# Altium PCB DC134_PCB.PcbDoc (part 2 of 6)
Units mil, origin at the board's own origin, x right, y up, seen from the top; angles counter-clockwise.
Board outline 4000 x 2750 mil, 6 copper layers (L1_Top Layer, L2_GND1, L3_Signal, L4_Plane, L5_GND2, L6_Bottom Layer), stack 60.4 mil thick; 404 components, 244 nets, 1547 pads, 694 vias.
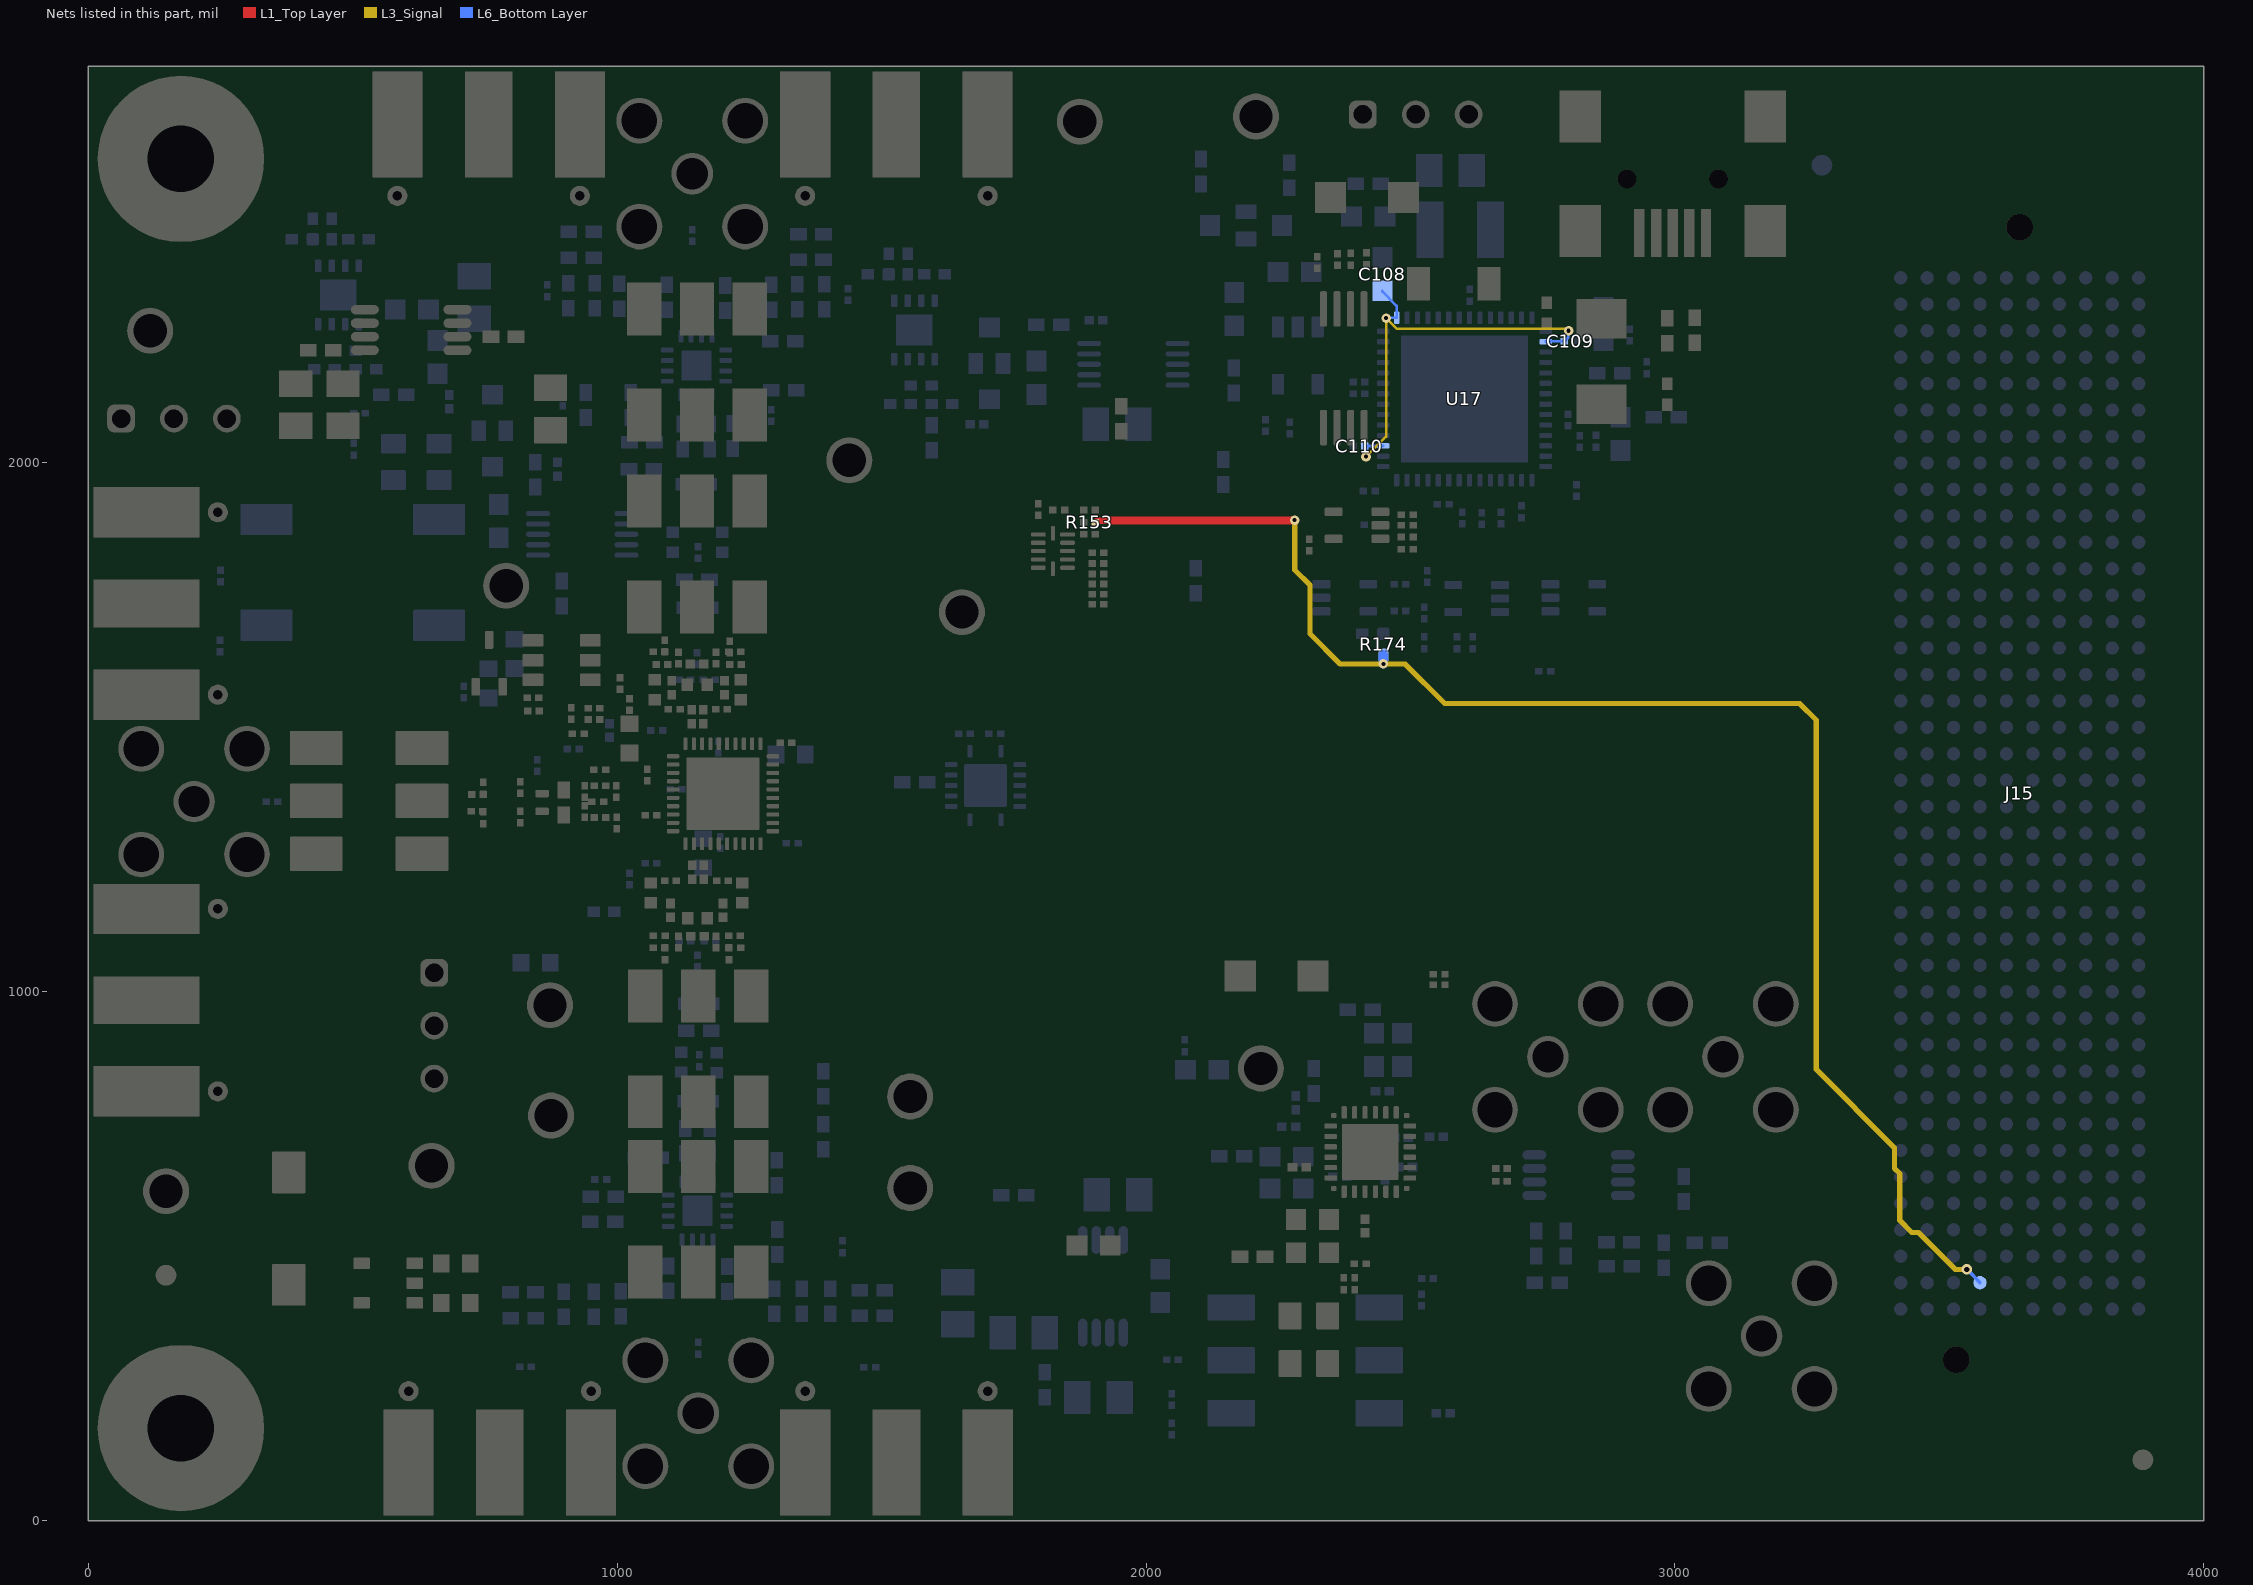
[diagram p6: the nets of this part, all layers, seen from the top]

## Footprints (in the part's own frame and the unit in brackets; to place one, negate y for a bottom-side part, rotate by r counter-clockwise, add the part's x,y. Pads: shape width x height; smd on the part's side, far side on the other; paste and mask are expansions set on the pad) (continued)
Johnson_142-0701-801#2 [mil] "Johnson Components recommended land pattern"
  rect 90x200 smd: 1(0,0)
  round 38 hole 18 mask+1.97: 2(-172.5,-135) 3(172.5,-135)
  rect 95x200 smd: 2(-172.5,0) 3(172.5,0)
  rect 95x200 smd far side: 4(-172.5,0) 5(172.5,0)
  L1_Top Layer lines w18: -172.5,0 -172.5,-135 ; 172.5,0 172.5,-135
  L6_Bottom Layer lines w18: -172.5,0 -172.5,-135 ; 172.5,0 172.5,-107 172.5,-135
  silkscreen extent -235,-170 235,100, body extent -190,-92 190,480, height 165
Keystone5010 [mil] "Keystone Multipurpose loops"
  round 87 hole 63: 1(0,0)
  silkscreen extent -70,-70 70,70, body extent -63,-63 63,62, height 319
Keystone5011 [mil] "Keystone Multipurpose loops"
  round 87 hole 63: 1(0,0)
  silkscreen extent -70,-70 70,70, body extent -63,-63 63,62, height 319
Keystone5013 [mil] "Keystone Multipurpose loops"
  round 87 hole 63: 1(0,0)
  silkscreen extent -70,-70 70,70, body extent -63,-63 63,62, height 319
Keystone_1902E [mil] "Hex Standoff, 4-40 threaded, nylon"
  round 1 on Mech4: 0(0,0)
  body extent -145,-126 146,126, height 1001
Kyocera_KC3225A [mm] "SMD, 4-Leads, Body 3.2x2.5mm"
  rrect11% 0.95x1.2 smd: 1(-0.875,1.1) 2(-0.875,-1.1) 3(0.875,-1.1) 4(0.875,1.1)
  silkscreen extent -1.7,-2.05 1.7,2.05, body extent -1.25,-1.6 1.25,1.6, height 1.01
Label_650x200 [mil] "Thermal Transfer Label"
  round 1 on Mech13: 0(0,0)
  silkscreen extent -325,-100 325,100, body extent -325,-100 325,100, height 1
LQG15WZ_02 [mm] "MuRata recommended land pattern"
  rrect29% 0.35x0.65 smd: 1(-0.425,0) 2(0.425,0)
  body extent -0.52,-0.32 0.52,0.32, height 0.6
LTST-C150_1206_Green [mm] "SMD, 2-Leads, Body 1.6x3.2mm"
  rect 1.5x1.5 smd: 1(-1.75,0) 2(1.75,0)
  silkscreen extent -3.3,-1.15 2.65,1.15, body extent -1.65,-0.85 1.65,0.85, height 1.2
MNC_CD542 [mil] "Mini-Circuits recommended land pattern 98-CD.doc rev K 11/06/06"
  rect 100x65 smd: 1(-100,100) 2(-100,0) 3(-100,-100) 4(100,-100) 5(100,0) 6(100,100)
  silkscreen extent -170,-165 170,165, body extent -141,-157 141,157, height 112
Murata_NFM31P [mm] "SMD, 3-Leads, Body 3.2x1.6mm"
  rect 0.95x1 smd paste-2 mask-2: 1(-1.725,0) 3(1.725,0)
  rect 1x0.7 smd paste-2 mask+0: 2(0,-0.65) 2(0,0.65)
  silkscreen extent -2.59,-1.2 2.59,1.2, body extent -1.7,-0.9 1.7,0.9, height 1.5
"NY PMS 440 0025 PH" [mm] "4-40 nylon screw and mounting hole"
  round 8 hole 3.2: 1(0,0)
  body extent -3.3,-3.3 3.3,3.3, height 2.69
RGE0024P [mm] "VQFN-24"
  rrect40% 0.6x0.25 smd: 1(-1.9,1.25) 2(-1.9,0.75) 3(-1.9,0.25) 4(-1.9,-0.25) 5(-1.9,-0.75) 6(-1.9,-1.25) 13(1.9,-1.25) 14(1.9,-0.75) 15(1.9,-0.25) 16(1.9,0.25) 17(1.9,0.75) 18(1.9,1.25)
  rrect40% 0.25x0.6 smd: 7(-1.25,-1.9) 8(-0.75,-1.9) 9(-0.25,-1.9) 10(0.25,-1.9) 11(0.75,-1.9) 12(1.25,-1.9) 19(1.25,1.9) 20(0.75,1.9) 21(0.25,1.9) 22(-0.25,1.9) 23(-0.75,1.9) 24(-1.25,1.9)
  rrect4% 2.7x2.7 smd paste-2.7: 25(0,0)
  rrect40% 0.25x0.25 smd: A1(-1.75,1.75) A2(-1.75,-1.75) A3(1.75,-1.75) A4(1.75,1.75)
  body extent -2,-2 2,2, height 0.9
RGT0016A_NV [mm] "QFN, 16-Leads, Body 3x3mm, Pitch 0.5mm, Thermal Pad 1.45x1.45mm, TI Recommended"
  rrect42% 0.6x0.24 smd: 1(-1.4,0.75) 2(-1.4,0.25) 3(-1.4,-0.25) 4(-1.4,-0.75) 9(1.4,-0.75) 10(1.4,-0.25) 11(1.4,0.25) 12(1.4,0.75)
  rrect42% 0.24x0.6 smd: 5(-0.75,-1.4) 6(-0.25,-1.4) 7(0.25,-1.4) 8(0.75,-1.4) 13(0.75,1.4) 14(0.25,1.4) 15(-0.25,1.4) 16(-0.75,1.4)
  rrect7% 1.34x1.34 on Bottom Paste: 17(0,0)
  rrect7% 1.45x1.45 smd paste-0.725: 17(0,0)
  silkscreen extent -1.72,-1.73 1.72,1.73, body extent -1.57,-1.57 1.58,1.58, height 1.01
RSB0040B [mm] "WQFN-40"
  rrect50% 0.6x0.2 smd: 1(-2.4,1.8) 2(-2.4,1.4) 3(-2.4,1) 4(-2.4,0.6) 5(-2.4,0.2) 6(-2.4,-0.2) 7(-2.4,-0.6) 8(-2.4,-1) 9(-2.4,-1.4) 10(-2.4,-1.8) 21(2.4,-1.8) 22(2.4,-1.4) 23(2.4,-1) 24(2.4,-0.6) 25(2.4,-0.2) 26(2.4,0.2) 27(2.4,0.6) 28(2.4,1) 29(2.4,1.4) 30(2.4,1.8)
  rrect50% 0.2x0.6 smd: 11(-1.8,-2.4) 12(-1.4,-2.4) 13(-1,-2.4) 14(-0.6,-2.4) 15(-0.2,-2.4) 16(0.2,-2.4) 17(0.6,-2.4) 18(1,-2.4) 19(1.4,-2.4) 20(1.8,-2.4) 31(1.8,2.4) 32(1.4,2.4) 33(1,2.4) 34(0.6,2.4) 35(0.2,2.4) 36(-0.2,2.4) 37(-0.6,2.4) 38(-1,2.4) 39(-1.4,2.4) 40(-1.8,2.4)
  rrect3% 3.5x3.5 smd paste-1.75: 41(0,0)
  body extent -2.5,-2.5 2.5,2.5, height 0.8
RUT0012A [mm] "QFN, 12-Leads, Body 1.7x2mm, Pitch 0.4mm, TI Recommended"
  rrect50% 0.7x0.2 smd: 1(-0.7,0.8) 2(-0.7,0.4) 3(-0.7,0) 4(-0.7,-0.4) 5(-0.7,-0.8) 7(0.7,-0.8) 8(0.7,-0.4) 9(0.7,0) 10(0.7,0.4) 11(0.7,0.8)
  rrect50% 0.2x0.7 smd: 6(0,-0.85) 12(0,0.85)
  silkscreen extent -0.9,-1.2 0.9,1.2, body extent -0.85,-1 0.85,1, height 0.55
RWA0014A [mm] "QFN, 14-Leads, Body 3.5x3.5mm, Pitch 0.5mm, Thermal Pad 2.05x2.05mm, TI Recommended"
  rrect42% 0.24x0.6 smd: 1(-0.75,1.65) 7(-0.75,-1.65) 8(0.75,-1.65) 14(0.75,1.65)
  rrect42% 0.6x0.24 smd: 2(-1.65,1) 3(-1.65,0.5) 4(-1.65,0) 5(-1.65,-0.5) 6(-1.65,-1) 9(1.65,-1) 10(1.65,-0.5) 11(1.65,0) 12(1.65,0.5) 13(1.65,1)
  rrect5% 2.05x2.05 smd paste-1.025: 15(0,0)
  silkscreen extent -1.98,-1.97 1.98,1.97, body extent -1.83,-1.83 1.82,1.82, height 0.81
Samtec_ASP-134488-01 [mm] "Connector, 1.27mm, 40x10, SMT"
  round 0.64 smd paste+0.125: A1(-5.715,24.765) A2(-5.715,23.495) A3(-5.715,22.225) A4(-5.715,20.955) A5(-5.715,19.685) A6(-5.715,18.415) A7(-5.715,17.145) A8(-5.715,15.875) A9(-5.715,14.605) A10(-5.715,13.335) A11(-5.715,12.065) A12(-5.715,10.795) A13(-5.715,9.525) A14(-5.715,8.255) A15(-5.715,6.985) A16(-5.715,5.715) A17(-5.715,4.445) A18(-5.715,3.175) A19(-5.715,1.905) A20(-5.715,0.635) A21(-5.715,-0.635) A22(-5.715,-1.905) A23(-5.715,-3.175) A24(-5.715,-4.445) A25(-5.715,-5.715) A26(-5.715,-6.985) A27(-5.715,-8.255) A28(-5.715,-9.525) A29(-5.715,-10.795) A30(-5.715,-12.065) A31(-5.715,-13.335) A32(-5.715,-14.605) A33(-5.715,-15.875) A34(-5.715,-17.145) A35(-5.715,-18.415) A36(-5.715,-19.685) A37(-5.715,-20.955) A38(-5.715,-22.225) A39(-5.715,-23.495) A40(-5.715,-24.765) B1(-4.445,24.765) B2(-4.445,23.495) B3(-4.445,22.225) B4(-4.445,20.955) B5(-4.445,19.685) B6(-4.445,18.415) B7(-4.445,17.145) B8(-4.445,15.875) B9(-4.445,14.605) B10(-4.445,13.335) B11(-4.445,12.065) B12(-4.445,10.795) B13(-4.445,9.525) B14(-4.445,8.255) B15(-4.445,6.985) B16(-4.445,5.715) B17(-4.445,4.445) B18(-4.445,3.175) B19(-4.445,1.905) B20(-4.445,0.635) B21(-4.445,-0.635) B22(-4.445,-1.905) B23(-4.445,-3.175) B24(-4.445,-4.445) B25(-4.445,-5.715) B26(-4.445,-6.985) B27(-4.445,-8.255) B28(-4.445,-9.525) B29(-4.445,-10.795) B30(-4.445,-12.065) B31(-4.445,-13.335) B32(-4.445,-14.605) B33(-4.445,-15.875) B34(-4.445,-17.145) B35(-4.445,-18.415) B36(-4.445,-19.685) B37(-4.445,-20.955) B38(-4.445,-22.225) B39(-4.445,-23.495) B40(-4.445,-24.765) C1(-3.175,24.765) C2(-3.175,23.495) C3(-3.175,22.225) C4(-3.175,20.955) C5(-3.175,19.685) C6(-3.175,18.415) C7(-3.175,17.145) C8(-3.175,15.875) C9(-3.175,14.605) C10(-3.175,13.335) C11(-3.175,12.065) C12(-3.175,10.795) C13(-3.175,9.525) C14(-3.175,8.255) C15(-3.175,6.985) C16(-3.175,5.715) C17(-3.175,4.445) C18(-3.175,3.175) C19(-3.175,1.905) C20(-3.175,0.635) C21(-3.175,-0.635) C22(-3.175,-1.905) C23(-3.175,-3.175) C24(-3.175,-4.445) C25(-3.175,-5.715) C26(-3.175,-6.985) C27(-3.175,-8.255) C28(-3.175,-9.525) C29(-3.175,-10.795) C30(-3.175,-12.065) C31(-3.175,-13.335) C32(-3.175,-14.605) C33(-3.175,-15.875) C34(-3.175,-17.145) C35(-3.175,-18.415) C36(-3.175,-19.685) C37(-3.175,-20.955) C38(-3.175,-22.225) C39(-3.175,-23.495) C40(-3.175,-24.765) D1(-1.905,24.765) D2(-1.905,23.495) D3(-1.905,22.225) D4(-1.905,20.955) D5(-1.905,19.685) D6(-1.905,18.415) D7(-1.905,17.145) D8(-1.905,15.875) D9(-1.905,14.605) D10(-1.905,13.335) D11(-1.905,12.065) D12(-1.905,10.795) D13(-1.905,9.525) D14(-1.905,8.255) D15(-1.905,6.985) D16(-1.905,5.715) D17(-1.905,4.445) D18(-1.905,3.175) D19(-1.905,1.905) D20(-1.905,0.635) D21(-1.905,-0.635) D22(-1.905,-1.905) D23(-1.905,-3.175) D24(-1.905,-4.445) D25(-1.905,-5.715) D26(-1.905,-6.985) D27(-1.905,-8.255) D28(-1.905,-9.525) D29(-1.905,-10.795) D30(-1.905,-12.065) D31(-1.905,-13.335) D32(-1.905,-14.605) D33(-1.905,-15.875) D34(-1.905,-17.145) D35(-1.905,-18.415) D36(-1.905,-19.685) D37(-1.905,-20.955) D38(-1.905,-22.225) D39(-1.905,-23.495) D40(-1.905,-24.765) E1(-0.635,24.765) E2(-0.635,23.495) E3(-0.635,22.225) E4(-0.635,20.955) E5(-0.635,19.685) E6(-0.635,18.415) E7(-0.635,17.145) E8(-0.635,15.875) E9(-0.635,14.605) E10(-0.635,13.335) E11(-0.635,12.065) E12(-0.635,10.795) E13(-0.635,9.525) E14(-0.635,8.255) E15(-0.635,6.985) E16(-0.635,5.715) E17(-0.635,4.445) E18(-0.635,3.175) E19(-0.635,1.905) E20(-0.635,0.635) E21(-0.635,-0.635) E22(-0.635,-1.905) E23(-0.635,-3.175) E24(-0.635,-4.445) E25(-0.635,-5.715) E26(-0.635,-6.985) E27(-0.635,-8.255) E28(-0.635,-9.525) E29(-0.635,-10.795) E30(-0.635,-12.065) E31(-0.635,-13.335) E32(-0.635,-14.605) E33(-0.635,-15.875) E34(-0.635,-17.145) E35(-0.635,-18.415) E36(-0.635,-19.685) E37(-0.635,-20.955) E38(-0.635,-22.225) E39(-0.635,-23.495) E40(-0.635,-24.765) F1(0.635,24.765) F2(0.635,23.495) F3(0.635,22.225) F4(0.635,20.955) F5(0.635,19.685) F6(0.635,18.415) F7(0.635,17.145) F8(0.635,15.875) F9(0.635,14.605) F10(0.635,13.335) F11(0.635,12.065) F12(0.635,10.795) F13(0.635,9.525) F14(0.635,8.255) F15(0.635,6.985) F16(0.635,5.715) F17(0.635,4.445) F18(0.635,3.175) F19(0.635,1.905) F20(0.635,0.635) F21(0.635,-0.635) F22(0.635,-1.905) F23(0.635,-3.175) F24(0.635,-4.445) F25(0.635,-5.715) F26(0.635,-6.985) F27(0.635,-8.255) F28(0.635,-9.525) F29(0.635,-10.795) F30(0.635,-12.065) F31(0.635,-13.335) F32(0.635,-14.605) F33(0.635,-15.875) F34(0.635,-17.145) F35(0.635,-18.415) F36(0.635,-19.685) F37(0.635,-20.955) F38(0.635,-22.225) F39(0.635,-23.495) F40(0.635,-24.765) G1(1.905,24.765) G2(1.905,23.495) G3(1.905,22.225) G4(1.905,20.955) G5(1.905,19.685) G6(1.905,18.415) G7(1.905,17.145) G8(1.905,15.875) G9(1.905,14.605) G10(1.905,13.335) G11(1.905,12.065) G12(1.905,10.795) G13(1.905,9.525) G14(1.905,8.255) G15(1.905,6.985) G16(1.905,5.715) G17(1.905,4.445) G18(1.905,3.175) G19(1.905,1.905) G20(1.905,0.635) G21(1.905,-0.635) G22(1.905,-1.905) G23(1.905,-3.175) G24(1.905,-4.445) G25(1.905,-5.715) G26(1.905,-6.985) G27(1.905,-8.255) G28(1.905,-9.525) G29(1.905,-10.795) G30(1.905,-12.065) G31(1.905,-13.335) G32(1.905,-14.605) G33(1.905,-15.875) G34(1.905,-17.145) G35(1.905,-18.415) G36(1.905,-19.685) G37(1.905,-20.955) G38(1.905,-22.225) G39(1.905,-23.495) G40(1.905,-24.765) H1(3.175,24.765) H2(3.175,23.495) H3(3.175,22.225) H4(3.175,20.955) H5(3.175,19.685) H6(3.175,18.415) H7(3.175,17.145) H8(3.175,15.875) H9(3.175,14.605) H10(3.175,13.335) H11(3.175,12.065) H12(3.175,10.795) H13(3.175,9.525) H14(3.175,8.255) H15(3.175,6.985) H16(3.175,5.715) H17(3.175,4.445) H18(3.175,3.175) H19(3.175,1.905) H20(3.175,0.635) H21(3.175,-0.635) H22(3.175,-1.905) H23(3.175,-3.175) H24(3.175,-4.445) H25(3.175,-5.715) H26(3.175,-6.985) H27(3.175,-8.255) H28(3.175,-9.525) H29(3.175,-10.795) H30(3.175,-12.065) H31(3.175,-13.335) H32(3.175,-14.605) H33(3.175,-15.875) H34(3.175,-17.145) H35(3.175,-18.415) H36(3.175,-19.685) H37(3.175,-20.955) H38(3.175,-22.225) H39(3.175,-23.495) H40(3.175,-24.765) J1(4.445,24.765) J2(4.445,23.495) J3(4.445,22.225) J4(4.445,20.955) J5(4.445,19.685) J6(4.445,18.415) J7(4.445,17.145) J8(4.445,15.875) J9(4.445,14.605) J10(4.445,13.335) J11(4.445,12.065) J12(4.445,10.795) J13(4.445,9.525) J14(4.445,8.255) J15(4.445,6.985) J16(4.445,5.715) J17(4.445,4.445) J18(4.445,3.175) J19(4.445,1.905) J20(4.445,0.635) J21(4.445,-0.635) J22(4.445,-1.905) J23(4.445,-3.175) J24(4.445,-4.445) J25(4.445,-5.715) J26(4.445,-6.985) J27(4.445,-8.255) J28(4.445,-9.525) J29(4.445,-10.795) J30(4.445,-12.065) J31(4.445,-13.335) J32(4.445,-14.605) J33(4.445,-15.875) J34(4.445,-17.145) J35(4.445,-18.415) J36(4.445,-19.685) J37(4.445,-20.955) J38(4.445,-22.225) J39(4.445,-23.495) J40(4.445,-24.765) K1(5.715,24.765) K2(5.715,23.495) K3(5.715,22.225) K4(5.715,20.955) K5(5.715,19.685) K6(5.715,18.415) K7(5.715,17.145) K8(5.715,15.875) K9(5.715,14.605) K10(5.715,13.335) K11(5.715,12.065) K12(5.715,10.795) K13(5.715,9.525) K14(5.715,8.255) K15(5.715,6.985) K16(5.715,5.715) K17(5.715,4.445) K18(5.715,3.175) K19(5.715,1.905) K20(5.715,0.635) K21(5.715,-0.635) K22(5.715,-1.905) K23(5.715,-3.175) K24(5.715,-4.445) K25(5.715,-5.715) K26(5.715,-6.985) K27(5.715,-8.255) K28(5.715,-9.525) K29(5.715,-10.795) K30(5.715,-12.065) K31(5.715,-13.335) K32(5.715,-14.605) K33(5.715,-15.875) K34(5.715,-17.145) K35(5.715,-18.415) K36(5.715,-19.685) K37(5.715,-20.955) K38(5.715,-22.225) K39(5.715,-23.495) K40(5.715,-24.765)
  round 1.27 hole 1.27 unplated mask+0: MH1(0,27.19) MH2(3.05,-27.19)
  silkscreen extent -8.25,-27.89 7.34,28.78, body extent -7.34,-27.89 7.34,28.78, height 7.11
SW_EVQ5PN04K [mm] "SMD, 2-Leads, Body 6x3.5mm"
  rrect6% 2x1.6 smd: 1(-2.7,0) 2(2.7,0)
  silkscreen extent -3,-1.75 3,1.75, body extent -3.6,-1.75 3.6,1.75, height 4.3
TE_87224-3 [mil] "Header, 2.54mm, 3x1, TH"
  rrect50% 52.5x52.5 hole 35: 1(-100,0)
  round 52.5 hole 35: 2(0,0) 3(100,0)
  silkscreen extent -142,-46 142,55, body extent -142,-46 142,46, height 408
TI_Stacked_Overlay_Small [mil]
  silkscreen extent -418,-98 418,98
TSSOP-8 [mm] "TSSOP, 8-Leads, Body 3.1x4.5mm (max), Pitch 0.65mm, IPC Medium Density"
  rrect50% 1.7x0.35 smd: 1(-2.85,0.975) 2(-2.85,0.325) 3(-2.85,-0.325) 4(-2.85,-0.975) 5(2.85,-0.975) 6(2.85,-0.325) 7(2.85,0.325) 8(2.85,0.975)
  silkscreen extent -2.97,-1.55 1.6,1.83, body extent -3.2,-1.55 3.2,1.55, height 1.07
VQFN-56 [mm] "VQFN, 56-Leads, Body 8x8mm, Pitch 0.5mm"
  rrect40% 0.6x0.25 smd: 1(-3.9,3.25) 2(-3.9,2.75) 3(-3.9,2.25) 4(-3.9,1.75) 5(-3.9,1.25) 6(-3.9,0.75) 7(-3.9,0.25) 8(-3.9,-0.25) 9(-3.9,-0.75) 10(-3.9,-1.25) 11(-3.9,-1.75) 12(-3.9,-2.25) 13(-3.9,-2.75) 14(-3.9,-3.25) 29(3.9,-3.25) 30(3.9,-2.75) 31(3.9,-2.25) 32(3.9,-1.75) 33(3.9,-1.25) 34(3.9,-0.75) 35(3.9,-0.25) 36(3.9,0.25) 37(3.9,0.75) 38(3.9,1.25) 39(3.9,1.75) 40(3.9,2.25) 41(3.9,2.75) 42(3.9,3.25)
  rrect40% 0.25x0.6 smd: 15(-3.25,-3.9) 16(-2.75,-3.9) 17(-2.25,-3.9) 18(-1.75,-3.9) 19(-1.25,-3.9) 20(-0.75,-3.9) 21(-0.25,-3.9) 22(0.25,-3.9) 23(0.75,-3.9) 24(1.25,-3.9) 25(1.75,-3.9) 26(2.25,-3.9) 27(2.75,-3.9) 28(3.25,-3.9) 43(3.25,3.9) 44(2.75,3.9) 45(2.25,3.9) 46(1.75,3.9) 47(1.25,3.9) 48(0.75,3.9) 49(0.25,3.9) 50(-0.25,3.9) 51(-0.75,3.9) 52(-1.25,3.9) 53(-1.75,3.9) 54(-2.25,3.9) 55(-2.75,3.9) 56(-3.25,3.9)
  rect 6.1x6.1 smd paste-6.1: 57(0,0)
  rect 0.973x0.973 on Bottom Paste: ""(-2.346,-2.346) ""(-2.346,-1.173) ""(-2.346,0) ""(-2.346,1.173) ""(-2.346,2.346) ""(-1.173,-2.346) ""(-1.173,-1.173) ""(-1.173,0) ""(-1.173,1.173) ""(-1.173,2.346) ""(0,-2.346) ""(0,-1.173) ""(0,0) ""(0,1.173) ""(0,2.346) ""(1.173,-2.346) ""(1.173,-1.173) ""(1.173,0) ""(1.173,1.173) ""(1.173,2.346) ""(2.346,-2.346) ""(2.346,-1.173) ""(2.346,0) ""(2.346,1.173) ""(2.346,2.346)
  body extent -4.04,-4.04 4.04,4.04, height 1
WEEE_Minimum [mil] "WEEElie bin"
  silkscreen extent -95,-172 99,104
XTAL_ABM3 [mm] "Abracon recommended land pattern 12.28.10"
  rect 1.9x2.4 smd: 1(-2.05,0) 2(2.05,0)
  silkscreen extent -2.67,-1.78 2.67,1.78, body extent -2.6,-1.7 2.6,1.7, height 1.3

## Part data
C1 C2 C3 C5 C6 C7 C8 C9 C10 C11 C13 C14 C15 C16 C21 C23 C24 C26 C37 C38 C40 C41 C42 C45 C48 C86 C97 C100 C105 C106 C107 C109 C110 C112 C114 C115 C116 C120 C121 C122 C123 C124: library part CMP-0064970-1, "CAP, CERM, 0.1 uF, 16 V,+/- 10%, X7R, 0201", Cap_Case=0201, Manufacturer=MuRata, Supplier Part Number 1=81-GRM033Z71C104KE4D, TempCo=X7R, Tolerance_%=10%, Value1=Unknown, Value2=16V, ValueDisplayed=0.1uF
C4 C12: library part CMP-0009763-1, "CAP, CERM, 100 pF, 25 V, +/- 10%, X7R, 0201", Cap_Case=0201, Manufacturer=MuRata, Supplier Part Number 1=490-3172-1-ND, TempCo=X7R, Tolerance_%=10%, Value1=Unknown, Value2=25V, ValueDisplayed=100pF
C17 C18 C19 C20 C22 C49 C50 C53 C54 C55 C58 C59 C61 C63 C65 C66 C102 C103: library part CMP-0006607-2, "CAP, CERM, 0.1 uF, 25 V, +/- 10%, X5R, 0402", Cap_Case=0402, Manufacturer=MuRata, Supplier Part Number 1=490-5920-1-ND, TempCo=X5R, Tolerance_%=10%, Value1=Unknown, Value2=25V, ValueDisplayed=0.1uF
C25: library part CMP-0006380-2, "CAP, CERM, 39 pF, 25 V, +/- 5%, C0G/NP0, 0402", Cap_Case=0402, Manufacturer=MuRata, Supplier Part Number 1=81-GRM1555C1E390JA1D, TempCo=C0G/NP0, Tolerance_%=5%, Value1=Unknown, Value2=25V, ValueDisplayed=39pF
C27 C31 C34 C70 C75 C79: library part CMP-0006372-2, "CAP, CERM, 1 uF, 6.3 V, +/- 20%, X5R, 0402", Cap_Case=0402, Manufacturer=MuRata, Supplier Part Number 1=490-10006-1-ND, TempCo=X5R, Tolerance_%=20%, Value1=Unknown, Value2=6.3V, ValueDisplayed=1uF
C28 C32 C35: library part CMP-0007347-5, "CAP, CERM, 4.7 uF, 25 V, +/- 10%, X5R, 0603", Cap_Case=0603, Manufacturer=MuRata, Supplier Part Number 1=490-7203-1-ND, TempCo=X5R, Tolerance_%=10%, Value1=Unknown, Value2=25V, ValueDisplayed=4.7uF
C29 C30 C33 C36 C74 C76 C78 C80: library part CMP-0009719-2, "CAP, CERM, 0.1 uF, 25 V, +/- 10%, X5R, 0201", Cap_Case=0201, Manufacturer=MuRata, Supplier Part Number 1=GRM033R61E104KE14D-ND, TempCo=X5R, Tolerance_%=10%, Value1=Unknown, Value2=25V, ValueDisplayed=0.1uF
C39 C43 C44 C47 C99 C101: library part CMP-0007497-5, "CAP, CERM, 10 uF, 10 V, +/- 20%, X7R, 0603", Cap_Case=0603, Manufacturer=MuRata, Supplier Part Number 1=81-GRM188Z71A106MA3D, TempCo=X7R, Tolerance_%=20%, Value1=Unknown, Value2=10V, ValueDisplayed=10uF
C46: library part CMP-0006624-2, "CAP, CERM, 1 uF, 6.3 V, +/- 20%, X7R, 0402", Cap_Case=0402, Manufacturer=MuRata, Supplier Part Number 1=490-9665-1-ND, TempCo=X7R, Tolerance_%=20%, Value1=Unknown, Value2=6.3V, ValueDisplayed=1uF
C51 C56: library part CMP-0006377-2, "CAP, CERM, 33 pF, 25 V, +/- 5%, C0G/NP0, 0402", Cap_Case=0402, Manufacturer=MuRata, Supplier Part Number 1=81-GRM1555C1E330JA1D, TempCo=C0G/NP0, Tolerance_%=5%, Value1=Unknown, Value2=25V, ValueDisplayed=33pF
C52 C57: library part CMP-0006425-2, "CAP, CERM, 180 pF, 50 V, +/- 5%, C0G/NP0, 0402", Cap_Case=0402, Manufacturer=MuRata, Supplier Part Number 1=490-3231-1-ND, TempCo=C0G/NP0, Tolerance_%=5%, Value1=Unknown, Value2=50V, ValueDisplayed=180pF
C60 C62 C64: library part CMP-0006607-2, "CAP, CERM, 0.1 uF, 25 V, +/- 10%, X5R, 0402", Cap_Case=0402, Manufacturer=MuRata, Supplier Part Number 1=490-5920-1-ND, TempCo=X5R, Tolerance_%=10%, Value1=Unknown, Value2=25V
C67: library part CMP-0009208-2, "CAP, CERM, 47 uF, 10 V, +/- 10%, X5R, 1210", Cap_Case=1210, Manufacturer=MuRata, Supplier Part Number 1=81-GRM32ER61A476KE20, TempCo=X5R, Tolerance_%=10%, Value1="0.001 ohm", Value2=10V, ValueDisplayed=47uF
C68 C87 C89: library part CMP-0008391-2, "CAP, CERM, 22 uF, 6.3 V, +/- 20%, X5R, 0805", Cap_Case=0805, Manufacturer="Taiyo Yuden", Supplier Part Number 1=587-1305-1-ND, TempCo=X5R, Tolerance_%=20%, Value1=Unknown, Value2=6.3V, ValueDisplayed=22uF
C69: library part CMP-0007318-5, "CAP, CERM, 10 uF, 10 V, +/- 20%, X5R, 0603", Cap_Case=0603, Manufacturer=MuRata, TempCo=X5R, Tolerance_%=20%, Value1=Unknown, Value2=10V, ValueDisplayed=10uF
C71 C72: library part capcc03298, "CAP CER 4.7UF 10V X5R 0402", Manufacturer="TDK Corporation", Operating Temperature="-55°C ~ 85°C", Package / Case=0402, Ratings=-, Temperature Coefficient=X5R, Tolerance=±10%, Voltage - Rated=10V
C73 C77: library part capcc02726, "CAP CER 1UF 10V X6S 0402", Manufacturer="TDK Corporation", Operating Temperature="-55°C ~ 105°C", Package / Case=0402, Ratings=-, Temperature Coefficient=X6S, Tolerance=±10%, Voltage - Rated=10V
C81 C82 C91 C92: library part CMP-0007311-5, "CAP, CERM, 4.7 uF, 6.3 V, +/- 10%, X5R, 0603", Cap_Case=0603, Manufacturer=MuRata, Supplier Part Number 1=490-3297-1-ND, TempCo=X5R, Tolerance_%=10%, Value1="0.005 ohm", Value2=6.3V, ValueDisplayed=4.7uF
C83 C84: library part CMP-0006831-4, "CAP, CERM, 1 uF, 16 V, +/- 10%, X7R, 0603", Cap_Case=0603, Manufacturer="Wurth Elektronik", Supplier Part Number 1=710-885012206052, TempCo=X7R, Tolerance_%=10%, Value1=Unknown, Value2=16V, ValueDisplayed=1uF
C85 C88 C90 C93 C94 C95 C96: library part CMP-0007691-2, "CAP, CERM, 10 uF, 10 V, +/- 10%, X7R, 0805", Cap_Case=0805, Manufacturer="Wurth Elektronik", Supplier Part Number 1=710-885012207026, TempCo=X7R, Tolerance_%=10%, Value1=Unknown, Value2=10V, ValueDisplayed=10uF
C98: library part CMP-0009762-1, "CAP, CERM, 100 pF, 25 V, +/- 5%, C0G/NP0, 0201", Cap_Case=0201, Manufacturer=MuRata, Supplier Part Number 1=81-GRM033R71E101JA1D, TempCo=C0G/NP0, Tolerance_%=5%, Value1=Unknown, Value2=25V, ValueDisplayed=100pF
C104: library part CMP-0064957-1, "CAP, CERM, 100 uF, 6.3 V,+/- 20%, X5R, 1206", Cap_Case=1206, Manufacturer=TDK, Supplier Part Number 1=445-6008-1-ND, TempCo=X5R, Tolerance_%=20%, Value1=Unknown, Value2=6.3V, ValueDisplayed=100uF
C108: library part CMP-0007008-5, "CAP, CERM, 3.3 uF, 25 V, +/- 10%, X5R, 0603", Cap_Case=0603, Manufacturer=TDK, Supplier Part Number 1=445-14141-1-ND, TempCo=X5R, Tolerance_%=10%, Value1=Unknown, Value2=25V, ValueDisplayed=3.3uF
C111 C113: library part CMP-0064936-4, "CAP, CERM, 4.7 uF, 16 V,+/- 10%, X7R, 0603", Cap_Case=0603, Manufacturer=MuRata, TempCo=X7R, Tolerance_%=10%, Value1=Unknown, Value2=16V, ValueDisplayed=4.7uF
C117: library part CMP-0085847-1, "CAP, CERM, 100 pF, 25 V,+/- 5%, C0G/NP0, 0201", Cap_Case=0201, Manufacturer=Yageo, TempCo=C0G/NP0, Tolerance_%=5%, Value2=25V, ValueDisplayed=100pF
C118 C119: library part CMP-0006247-2, "CAP, CERM, 18 pF, 50 V, +/- 5%, C0G/NP0, 0402", Cap_Case=0402, Manufacturer=TDK, Supplier Part Number 1=445-1238-1-ND, TempCo=C0G/NP0, Tolerance_%=5%, Value1=Unknown, Value2=50V, ValueDisplayed=18pF
C125 C126: library part capcc05563, "CAP CER 10000PF 10V X7R 0402", Manufacturer="KYOCERA AVX", Operating Temperature="-55°C ~ 125°C", Package / Case=0402, Ratings=-, Temperature Coefficient=X7R, Tolerance=±5%, Voltage - Rated=10V
D1 D2: library part CMP-0002920-2, "LED, Green, SMD", Color=Green, Manufacturer=LiteOn, Value1=W, Value2=2V
FB1 FB2 FB3: library part CMP-0001934-2, "FILTER LC HIGH FREQ 27uF 1206", Manufacturer=MuRata, Supplier Part Number 1=490-6984-1-ND
FID1 FID2 FID3: library part CMP-0077181-1, "Fiducial mark.  There is nothing to buy or mount.", Manufacturer=N/A
H1 H2: library part CMP-0003617-1, "Machine Screw, Round, #4-40 x 1/4, Nylon, Philips panhead", Manufacturer="B&F Fastener Supply", Supplier Part Number 1=H542-ND
H3 H4: library part CMP-0003611-1, Manufacturer=Keystone, Supplier Part Number 1=36-1902E-ND
J1 J3 J4 J6 J8 J10: library part CMP-0055828-1, "Connector, End launch SMA, 50 ohm, SMT", Manufacturer="Cinch Connectivity", Supplier Part Number 1=J502-ND
J2 J5 J7 J9 J11 J12: library part CMP-0055833-1, "SMA Straight Jack, Gold, 50 Ohm, TH", Manufacturer="Amphenol RF", Supplier Part Number 1=ARFX1231-ND
J13 J14 J16: library part CMP-0078139-1, "Header, 2.54mm, 3x1, Gold, TH", Color=Black, Current_A=3A, Manufacturer="TE Connectivity", Supplier Part Number 1=A26545-ND, Voltage_V=750V
J15: library part CMP-0075635-1, "Connector, 1.27mm, 40x10, Black, SMT", Color=Black, Manufacturer=Samtec, Supplier Part Number 1=79X1313
J17: library part CMP-0054920-2, "Connector, Receptacle, Mini-USB Type B, R/A, Top Mount SMT", Manufacturer="TE Connectivity", Supplier Part Number 1=A31727CT-ND
L1 L2 L3 L4 L5 L6: library part CMP-0058650-1, "Inductor, Multilayer, Air Core, 180 nH, 0.14 A, 3.38 ohm, SMD", Manufacturer=MuRata, Supplier Part Number 1=490-2638-1-ND, Value1="3.38 ohm", Value2=0.14A, ValueDisplayed=180nH
L7: library part CMP-0080278-3, "Inductor, Multilayer, Air Core, 43 nH, 0.19 A, 1.6 ohm, AEC-Q200 Grade 1, SMD", Manufacturer=MuRata, Value1="1.6 ohm", Value2=0.19A, ValueDisplayed=43nH
L8 L9 L10: library part CMP-0077879-1, "Ferrite Bead, 120 ohm @ 100 MHz, 1.9 A, 0603", Manufacturer=MuRata, Supplier Part Number 1=490-13261-1-ND, Value1="0.04 ohm", Value2=1.9A, ValueDisplayed="120 ohm"
L11 L12 L13 L14: library part CMP-0058651-1, "Inductor, Multilayer, Air Core, 220 nH, 0.12 A, 3.77 ohm, SMD", Manufacturer=MuRata, Supplier Part Number 1=490-2639-1-ND, Value1="3.77 ohm", Value2=0.12A, ValueDisplayed=220nH
L15 L18 L19 L20: library part CMP-0003214-1, "Ferrite Bead, 120 ohm @ 100 MHz, 0.5 A, 0402", Manufacturer="Wurth Elektronik", Supplier Part Number 1=710-74279271, Value1="0.2 ohm", Value2=0.5A, ValueDisplayed="120 ohm"
LBL1: library part CMP-0003625-1, "Thermal Transfer Printable Labels, 0.650\" W x 0.200\" H - 10,000 per roll", Manufacturer=Brady, Supplier Part Number 1=97C5133
Logo1: library part CMP-0074838-1, "Texas Instrument Corporate Signature"
Logo2: library part CMP-0074844-1
Logo3: library part CMP-0074847-1, "FCC_disclaimer"
Logo4: library part CMP-0074769-1
R1 R2 R3 R6 R9 R10 R13 R14 R15 R16 R17 R20 R23 R24 R27 R28 R31 R32 R33 R35 R36 R40 R41 R43 R45 R51 R52 R53 R54 R55 R60 R61 R63 R64 R68 R70 R75 R76 R77 R93 R95 R108 R112 R130 R135 R136 R137 R138 R139 R141 R142 R143 R144 R145 R146 R148 R151 R152 R153 R158 R159 R163 R167 R168 R169 R170: library part CMP-0027008-4, "RES, 0, 5%, 0.05 W, 0201", Manufacturer=Vishay-Dale, Power_W=50mW, Supplier Part Number 1=72M6743, TempCo=ppm/C, Tolerance_%=5%, Value2=0.05W, Value_Code=0000, ValueDisplayed=0
R4 R11 R18 R25: library part CMP-0028006-1, "RES, 33.0, 1%, 0.05 W, 0201", Manufacturer="Yageo America", Power_W=50mW, Supplier Part Number 1=603-RC0201FR-7D33RL, TempCo="200 ppm/C", Tolerance_%=1%, Value2=0.05W, Value_Code=33R0, ValueDisplayed=33.0
R5 R12 R19 R26 R48 R49: library part CMP-0027946-1, "RES, 10.0, 1%, 0.05 W, 0201", Manufacturer="Yageo America", Power_W=50mW, Supplier Part Number 1=603-RC0201FR-7D10RL, TempCo="350 ppm/C", Tolerance_%=1%, Value2=0.05W, Value_Code=10R0, ValueDisplayed=10.0
R7 R8 R21 R22: library part CMP-0027524-1, "RES, 25.5, 1%, 0.05 W, 0201", Manufacturer="Yageo America", Power_W=50mW, Supplier Part Number 1=YAG2539CT-ND, TempCo="200 ppm/C", Tolerance_%=1%, Value2=0.05W, Value_Code=25R5, ValueDisplayed=25.5
R29 R30 R46 R47 R50 R65 R67 R140: library part CMP-0028028-1, "RES, 49.9, 1%, 0.05 W, 0201", Manufacturer="Yageo America", Power_W=50mW, Supplier Part Number 1=603-RC0201FR-7D49R9L, TempCo="200 ppm/C", Tolerance_%=1%, Value2=0.05W, Value_Code=49R9, ValueDisplayed=49.9
R34 R42: library part CMP-0026453-2, "RES, 56.2 k, 1%, 0.063 W, AEC-Q200 Grade 0, 0402", Manufacturer=Vishay-Dale, Power_W=63mW, Supplier Part Number 1=541-56.2KLCT-ND, TempCo="100 ppm/C", Tolerance_%=1%, Value2=0.063W, Value_Code=56k2, ValueDisplayed=56.2k
R37 R44: library part CMP-0026196-2, "RES, 24.9 k, 1%, 0.063 W, AEC-Q200 Grade 0, 0402", Manufacturer=Vishay-Dale, Power_W=63mW, Supplier Part Number 1=541-24.9KLCT-ND, TempCo="100 ppm/C", Tolerance_%=1%, Value2=0.063W, Value_Code=24k9, ValueDisplayed=24.9k
R38 R39 R66 R69 R127: library part CMP-0027453-1, "RES, 1.00 k, 1%, 0.05 W, 0201", Manufacturer="Yageo America", Power_W=50mW, Supplier Part Number 1=311-1KMCT-ND, TempCo="200 ppm/C", Tolerance_%=1%, Value2=0.05W, Value_Code=1k00, ValueDisplayed=1.00k
R56 R58 R62 R71 R72 R73 R74: library part CMP-0028031-1, "RES, 4.70 k, 1%, 0.05 W, 0201", Manufacturer="Yageo America", Power_W=50mW, Supplier Part Number 1=603-RC0201FR-7D4K7L, TempCo="200 ppm/C", Tolerance_%=1%, Value2=0.05W, Value_Code=4k70, ValueDisplayed=4.70k
R57: library part CMP-0023343-3, "RES, 0, 1%, 0.1 W, AEC-Q200 Grade 0, 0603", Manufacturer="Stackpole Electronics Inc", Power_W=100mW, Supplier Part Number 1=RMCF0603ZT0R00CT-ND, TempCo=ppm/C, Tolerance_%=1%, Value2=0.1W, Value_Code=0
R59 R114: library part CMP-0026725-1, "RES, 1.00 k, 1%, 0.0625 W, 0402", Manufacturer="Yageo America", Power_W=62.5mW, Supplier Part Number 1=311-1.00KLRCT-ND, TempCo="100 ppm/C", Tolerance_%=1%, Value2=0.0625W, Value_Code=1k00, ValueDisplayed=1.00k
R78 R79: library part CMP-0065361-1, "RES, 0, 5%, .05 W, AEC-Q200 Grade 0, 0201", Manufacturer=Panasonic, Power_W=50mW, Supplier Part Number 1=P15979CT-ND, TempCo=ppm/C, Tolerance_%=5%, Value2=.05W, Value_Code=0000, ValueDisplayed=0
R80 R96 R97: library part CMP-0026402-2, "RES, 499, 1%, 0.063 W, AEC-Q200 Grade 0, 0402", Manufacturer=Vishay-Dale, Power_W=63mW, Supplier Part Number 1=541-499LCT-ND, TempCo="100 ppm/C", Tolerance_%=1%, Value2=0.063W, Value_Code=499R, ValueDisplayed=499
R81 R85 R94 R98 R102 R111: library part CMP-0026822-3, "RES, 0, 5%, 0.063 W, AEC-Q200 Grade 0, 0402", Manufacturer=Vishay-Dale, Power_W=63mW, Supplier Part Number 1=541-0.0JCT-ND, TempCo="200 ppm/C", Tolerance_%=5%, Value2=0.063W, Value_Code=0000, ValueDisplayed=0
R82 R91 R99 R109: library part CMP-0026462-2, "RES, 59.0, 1%, 0.063 W, AEC-Q200 Grade 0, 0402", Manufacturer=Vishay-Dale, Power_W=63mW, Supplier Part Number 1=541-59.0LCT-ND, TempCo="100 ppm/C", Tolerance_%=1%, Value2=0.063W, Value_Code=59R0, ValueDisplayed=59.0
R83 R92 R100 R110: library part CMP-0026404-2, "RES, 49.9, 1%, 0.063 W, AEC-Q200 Grade 0, 0402", Manufacturer=Vishay-Dale, Power_W=63mW, Supplier Part Number 1=541-49.9LCT-ND, TempCo="100 ppm/C", Tolerance_%=1%, Value2=0.063W, Value_Code=49R9, ValueDisplayed=49.9
R84 R90 R101 R107: library part CMP-0026320-2, "RES, 37.4, 1%, 0.063 W, AEC-Q200 Grade 0, 0402", Manufacturer=Vishay-Dale, Power_W=63mW, Supplier Part Number 1=541-37.4LCT-ND, TempCo="100 ppm/C", Tolerance_%=1%, Value2=0.063W, Value_Code=37R4, ValueDisplayed=37.4
R86 R88 R103 R105: library part CMP-0026159-2, "RES, 200, 1%, 0.063 W, AEC-Q200 Grade 0, 0402", Manufacturer=Vishay-Dale, Power_W=63mW, Supplier Part Number 1=541-200LCT-ND, TempCo="100 ppm/C", Tolerance_%=1%, Value2=0.063W, Value_Code=200R, ValueDisplayed=200
R87 R104: library part CMP-0026382-2, "RES, 442, 1%, 0.063 W, AEC-Q200 Grade 0, 0402", Manufacturer=Vishay-Dale, Power_W=63mW, Supplier Part Number 1=541-442LCT-ND, TempCo="100 ppm/C", Tolerance_%=1%, Value2=0.063W, Value_Code=442R, ValueDisplayed=442
R89 R106: library part CMP-0026700-1, "RES, 4.70 k, 1%, 0.1 W, 0402", Manufacturer=Panasonic, Power_W=100mW, Supplier Part Number 1=P4.70KLCT-ND, TempCo="100 ppm/C", Tolerance_%=1%, Value2=0.1W, Value_Code=4k70, ValueDisplayed=4.70k
R113: library part CMP-0026402-2, "RES, 499, 1%, 0.063 W, AEC-Q200 Grade 0, 0402", Manufacturer=Vishay-Dale, Power_W=63mW, Supplier Part Number 1=541-499LCT-ND, TempCo="100 ppm/C", Tolerance_%=1%, Value2=0.063W, Value_Code=499R
R115 R117: library part CMP-0026822-3, "RES, 0, 5%, 0.063 W, AEC-Q200 Grade 0, 0402", Manufacturer=Vishay-Dale, PartNumber=CRCW04020000Z0ED, Power_W=63mW, Supplier Part Number 1=541-0.0JCT-ND, TempCo="200 ppm/C", Tolerance_%=5%, Value2=0.063W, Value_Code=0000, ValueDisplayed=0
R116 R118 R121 R122 R175 R176: library part RSMD040201951, "RES SMD 10K OHM 1% 1/10W 0402", Manufacturer="Panasonic Electronic Components", Operating Temperature="-55°C ~ 155°C", Package / Case=0402, Power (Watts)="0.1W, 1/10W", Ratings=AEC-Q200, Temperature Coefficient=±100ppm/°C, Tolerance=±1%
R119 R120: library part RSMD040202026, "RES SMD 12.7K OHM 1% 1/10W 0402", Manufacturer="Panasonic Electronic Components", Operating Temperature="-55°C ~ 155°C", Package / Case=0402, Power (Watts)="0.1W, 1/10W", Ratings=AEC-Q200, Temperature Coefficient=±100ppm/°C, Tolerance=±1%
R123 R124 R125 R126: library part CMP-0027007-2, "RES, 0, 5%, 0.063 W, AEC-Q200 Grade 0, 0402", Manufacturer="KOA Speer", Power_W=63mW, Supplier Part Number 1=660-RK73Z1ETTP, TempCo=ppm/C, Tolerance_%=5%, Value2=0.063W, Value_Code=0000, ValueDisplayed=0
R128: library part CMP-0027731-1, "RES, 499, 1%, 0.05 W, 0201", Manufacturer="Yageo America", Power_W=50mW, Supplier Part Number 1=YAG2700CT-ND, TempCo="200 ppm/C", Tolerance_%=1%, Value2=0.05W, Value_Code=499R, ValueDisplayed=499
R129: library part CMP-0027094-3, "RES, 2.0, 5%, 0.05 W, 0201", Manufacturer="Yageo America", Power_W=50mW, Supplier Part Number 1=RC0201JR-072RL-ND, TempCo="350 ppm/C", Tolerance_%=5%, Value2=0.05W, Value_Code=2R00, ValueDisplayed=2.0
R131: library part CMP-0027940-1, "RES, 9.76 k, 1%, 0.05 W, 0201", Manufacturer="Yageo America", Power_W=50mW, Supplier Part Number 1=YAG2860CT-ND, TempCo="200 ppm/C", Tolerance_%=1%, Value2=0.05W, Value_Code=9k76, ValueDisplayed=9.76k
R132: library part CMP-0027360-2, "RES, 14.3 k, 1%, 0.05 W, 0201", Manufacturer="Yageo America", Power_W=50mW, Supplier Part Number 1=YAG2411CT-ND, TempCo="200 ppm/C", Tolerance_%=1%, Value2=0.05W, Value_Code=14k3, ValueDisplayed=14.3k
R133 R134: library part CMP-0022727-3, "RES, 0.05, 1%, 0.1 W, AEC-Q200 Grade 1, 0603", Manufacturer=Panasonic, Power_W=100mW, Supplier Part Number 1=P50LJCT-ND, TempCo="200 ppm/C", Tolerance_%=1%, Value2=0.1W, Value_Code=R050, ValueDisplayed=0.05
R147 R150: library part CMP-0026749-1, "RES, 10.0, 1%, 0.063 W, 0402", Manufacturer="KOA Speer", Power_W=63mW, Supplier Part Number 1=660-RK73H1ETTP10R0F, TempCo="100 ppm/C", Tolerance_%=1%, Value2=0.063W, Value_Code=10R0, ValueDisplayed=10.0
R149: library part CMP-0028071-1, "RES, 10.0 k, 1%, 0.05 W, 0201", Manufacturer="Yageo America", Power_W=50mW, Supplier Part Number 1=603-RC0201FS-7D10KL, TempCo="200 ppm/C", Tolerance_%=1%, Value2=0.05W, Value_Code=10k0, ValueDisplayed=10.0k
R154: library part CMP-0027954-1, "RES, 12.0 k, 1%, 0.05 W, 0201", Manufacturer="Yageo America", Power_W=50mW, Supplier Part Number 1=603-RC0201FR-7D12KL, TempCo="200 ppm/C", Tolerance_%=1%, Value2=0.05W, Value_Code=12k0, ValueDisplayed=12.0k
R155: library part CMP-0028084-1, "RES, 1.00 k, 1%, 0.05 W, 0201", Manufacturer="Yageo America", Power_W=50mW, Supplier Part Number 1=603-RC0201FS-7D1KL, TempCo="200 ppm/C", Tolerance_%=1%, Value2=0.05W, Value_Code=1k00, ValueDisplayed=1.00k
R156 R157: library part CMP-0026889-5, "RES, 2.0 k, 5%, 0.063 W, AEC-Q200 Grade 0, 0402", Manufacturer=Vishay-Dale, Power_W=63mW, Supplier Part Number 1=541-2.0KJCT-ND, TempCo="200 ppm/C", Tolerance_%=5%, Value2=0.063W, Value_Code=2k00, ValueDisplayed=2.0k
R160 R161 R162 R165 R166: library part CMP-0027945-1, "RES, 10.0 k, 1%, 0.05 W, 0201", Manufacturer="Yageo America", Power_W=50mW, Supplier Part Number 1=603-RC0201FR-7D10KL, TempCo="200 ppm/C", Tolerance_%=1%, Value2=0.05W, Value_Code=10k0, ValueDisplayed=10.0k
R164: library part CMP-0027995-1, "RES, 2.20 k, 1%, 0.05 W, 0201", Manufacturer="Yageo America", Power_W=50mW, Supplier Part Number 1=603-RC0201FR-7D2K2L, TempCo="200 ppm/C", Tolerance_%=1%, Value2=0.05W, Value_Code=2k20, ValueDisplayed=2.20k
R171 R172: library part CMP-0025885-5, "RES, 0, 5%, 0.1 W, 0603", Manufacturer=Yageo, Power_W=100mW, Supplier Part Number 1=311-0.0GRCT-ND, TempCo="200 ppm/C", Tolerance_%=5%, Value2=0.1W, Value_Code=0000, ValueDisplayed=0
R173 R174: library part CMP-0027004-2, "RES, 0, 5%, 0.063 W, 0402", Manufacturer="Yageo America", Power_W=63mW, Supplier Part Number 1=311-0.0JRCT-ND, TempCo="200 ppm/C", Tolerance_%=5%, Value2=0.063W, Value_Code=0000, ValueDisplayed=0
S1: library part CMP-0002323-1, "Switch, SPST-NO, Off-Mom, 0.05 A, 12 VDC, SMD", CurrentRating_mA=50A, Manufacturer=Panasonic, Supplier Part Number 1=P13595SCT-ND
T1 T2 T3 T4: library part CMP-0030461-2, "RF Transformer, 50 ohm, 2 to 775 MHz, SMT", Manufacturer=Minicircuits
T5: library part CMP-0086669-1, "Transformer 50Ω/0.03 to 125 MHz", Manufacturer=Mini-Circuits
TP1 TP3 TP4 TP5: library part CMP-0055148-1, "Test Point, Multipurpose, Black, TH", Color=Black, Manufacturer=Keystone, Supplier Part Number 1=36-5011-ND
TP2: library part CMP-0055150-2, "Test Point, Multipurpose, Orange, TH", Color=Orange, Manufacturer="Keystone Electronics", Supplier Part Number 1=36-5013-ND
TP6 TP7 TP8 TP9 TP10 TP11 TP12 TP13: library part CMP-0055147-2, "Test Point, Multipurpose, Red, TH", Color=Red, Manufacturer="Keystone Electronics", Supplier Part Number 1=36-5010-ND
U1: library part CMP-0076021-1, "2 Gbps LVDS/LVPECL/CML to LVDS Repeater/Translator, DGK0008A (VSSOP-8)", Alternate Manufacturer="Texas Instruments", Alternate PartNumber=SN65LVDS100DGK
U2: library part CMP-0074453-1, "One Channel Differential 2:1 Mux/Demux, RWA0014A (WQFN-14)", Alternate Manufacturer="Texas Instruments", Alternate PartNumber=HD3SS3411
U3: library part CMP-0750065-2, "CDCE6214WRGERQ1, RGE0024P (VQFN-24)", Alternate Manufacturer="Texas Instruments", Alternate PartNumber=CDCE6214WRGETQ1
U4: library part CMP-0080419-4, "18-bit 65 MSPS Low Noise Ultra-low Power Dual Channel ADC, RSB0040B (WQFN-40)", Alternate Manufacturer="Texas Instruments", Operating Temperature Range="-40 to 105 C"
U5: library part cmp00115, "Push-pull, supply voltage supervisor with manual reset", Alt Manufacturer=-, Manufacturer="Texas Instruments", Package=SOT-23
U6 U7: library part CMP-0065559-3, "High-Speed Differential I/O Amplifier, RGT0016A (VQFN-16)", Alternate Manufacturer="Texas Instruments", Alternate PartNumber=THS4541IRGTT
U8 U9: library part CMP-0065176-4, "#N/A", Alternate Manufacturer="Texas Instruments", Alternate PartNumber=TPS7A8001ADRBT
U10 U11: library part CMP-0072065-2, "Low Noise Negative Bias Generator, 8-pin Mini SOIC, Pb-Free", Manufacturer="Texas Instruments", PowerWise=N
U12: library part CMP-0035516-1, "Single Output LDO, 300 mA, Fixed 3.3 V Output, 2 to 5.5 V Input, with Low IQ, 5-pin SOT-23 (DBV), -40 to 125 degC, Green (RoHS & no Sb/Br)", Manufacturer="Texas Instruments"
U13: library part CMP-0013237-2, "Low Power, Precision, 105MHz, Voltage Feedback Op Amp, DBV0006A (SOT-6)", Alternate Manufacturer="Texas Instruments", Alternate PartNumber=OPA837IDBVT
U14: library part CMP-0032542-1, "30 ppm / degC Drift, 3.9 uA Voltage Reference, -40 to 125 degC, 3-pin SC70 (DCK), Green (RoHS & no Sb/Br)", Manufacturer="Texas Instruments", Rating=Catalog, Temp Coeff(Max)(ppm/ degree C)=30, Temp Coeff(Typ)(ppm/ degree C)=8
U15 U16: library part CMP-0037979-1, "High-Side Measurement, Bi-Directional Current / Power Monitor with I2C Interface, 2.7 to 5.5 V, -40 to 125 degC, 10-pin SOP (DGS10), Green (RoHS & no Sb/Br)", Quiescent Current (+/-)(Typ)(mA)=0.33, Rating=Catalog
U17: library part CMP-0081661-1, "Future Technology Devices International Ltd FT4232H Quad High Speed USB to Multipurpose UART/MPSSE IC, VQFN-56", Manufacturer=FTDI, Supplier Part Number 1=768-1277-ND
U18: library part CMP-0066443-2, "4-Bit Bidirectional Multi-Voltage Level Translator for Open-Drain & Push- Pull, RUT0012A (UQFN-12)", Alternate Manufacturer="Texas Instruments"
U19 U20 U22 U23: library part CMP-0051305-3, "Single Bus Buffer Gate With 3-State Outputs, DCK0005A, SMALL T&R", F @ Nom Voltage(Max)(Mhz)=150, Generic Part Number=SN74LVC1G125, ICC @ Nom Voltage(Max)(mA)=0.01, Manufacturer="Texas Instruments", Operating Temperature Range(C)="-40 to 125,-40 to 85", Rating=Catalog, tpd @ Nom Voltage(Max)(ns)=9,5.5,4.5,4, Voltage(Nom)(V)=1.8,2.5,3.3,5
U21: library part CMP-0081524-1, "1K Microwire Compatible Serial EEPROM, TSSOP-8", Manufacturer=Microchip, Supplier Part Number 1=93LC46B-I/ST-ND
Y1: library part CMP-0006126-3, "Clock Oscillator, 19.2 MHz, CMOS, 3.3V, SMD", Frequency_Fixed=19.2MHz, Frequency Stability=+/-50ppm, Manufacturer=Kyocera, Supplier Part Number 1=1253-1265-1-ND
Y2: library part CMP-0083654-1, "Oscillator, 125 MHz, 15 pF, SMD", Frequency_Fixed=125MHz, Frequency Stability="12 ppm", Load Capacitance="15 pF", Manufacturer="Abracon Corporation", Supplier Part Number 1=ABLNO-V-125.000MHZ-T2-ND
Y3: library part CMP-0090315-1, "Crystal 10MHz ±25ppm (Tol) ±30ppm (Stability) 12pF FUND 100Ohm 4-Pin Mini-CSMD T/R", Digikey Part Number=XC2604CT-ND, Frequency Stability=30ppm, Frequency Tolerance=25ppm, Frequency_Fixed=10MHz, Load Capacitance=12pF, Manufacturer=ECS, Mouser Part Number=520-100-12-33-AGNT, Operating Temperature Range="-40°C to +85°C"
Y4: library part CMP-0088179-1, "Ultra-low Phase Noise VCXO with Standby Mode", Frequency_Fixed=10MHz, Load Capacitance=15pF, Manufacturer="Crystek Corporation"
Y5: library part CMP-0004616-3, "Crystal, 12 MHz, 18 pF, SMD", Frequency_Fixed=12MHz, Frequency Stability=+/-30ppm, Manufacturer="Abracon Corporation", Supplier Part Number 1=535-10634-1-ND
ZZ1: library part CMP-0003616-3
ZZ2: library part CMP-0077236-1
ZZ3: library part CMP-0077237-1

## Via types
v1: diameter 18, hole 8, L1_Top Layer to L6_Bottom Layer, tented both sides, 448 vias
v2: diameter 20, hole 10, L1_Top Layer to L6_Bottom Layer, tented both sides, 182 vias
v3: diameter 19.68, hole 7.87, L1_Top Layer to L6_Bottom Layer, tented both sides, 42 vias
v4: diameter 19.68, hole 7.87, L1_Top Layer to L6_Bottom Layer, 20 vias
v5: diameter 18, hole 8, L1_Top Layer to L6_Bottom Layer, 2 vias

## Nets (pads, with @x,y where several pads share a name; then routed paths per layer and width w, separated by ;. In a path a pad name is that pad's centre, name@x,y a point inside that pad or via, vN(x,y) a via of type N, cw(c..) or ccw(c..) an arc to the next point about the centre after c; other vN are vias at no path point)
2.5V_FMC_VADJ: J15.G39 R153.1 R174.1 | length 2859.3
  L1_Top Layer w5: v1@2280,1891 v1(2281,1892)
  L1_Top Layer w12: R153.1@1904.02,1888 1907.02,1891 1931,1891
  L1_Top Layer w15: 1931,1891 v1@2280,1891
  L3_Signal w10: v1(2281,1892) 2281,1798 2310,1769 2310,1677 2367,1620 v1(2449.02,1620) 2490,1620 2565,1545 3236,1545 3267.5,1513.5 3267.5,852.93 3415.5,704.93 3415.5,665.82 3425.5,655.82 3425.5,567.5 3448,545 3460.43,545 3530.44,474.99 v2(3552,474.99)
  L6_Bottom Layer w6.6: v2@3553,474.99 J15.G39@3577,450.14
  L6_Bottom Layer w18: v1(2449.02,1620) R174.1@2449.02,1637.63
+1.8V_FTDI: C108.1 C109.2 C110.2 U17.2 U17.31 U17.43 | length 829.6
  L3_Signal w5: v1(2416,2012) 2454,2050 v1(2454,2274) 2474,2254 2795,2254 v1(2799,2250)
  L6_Bottom Layer w5: v1(2416,2012) 2416,2030.02 C110.2@2414.02,2032 2448.06,2032 U17.31@2448.47,2032.42 ; C108.1@2447,2325.5 2447,2324 2474.07,2296.94 U17.43@2474.06,2274.54 2454.54,2274.54 v1(2454,2274) ; U17.2@2755.56,2229.27 2756.29,2230 C109.2@2790.98,2230 2798.44,2237.46 2798.44,2249.44 v1(2799,2250)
